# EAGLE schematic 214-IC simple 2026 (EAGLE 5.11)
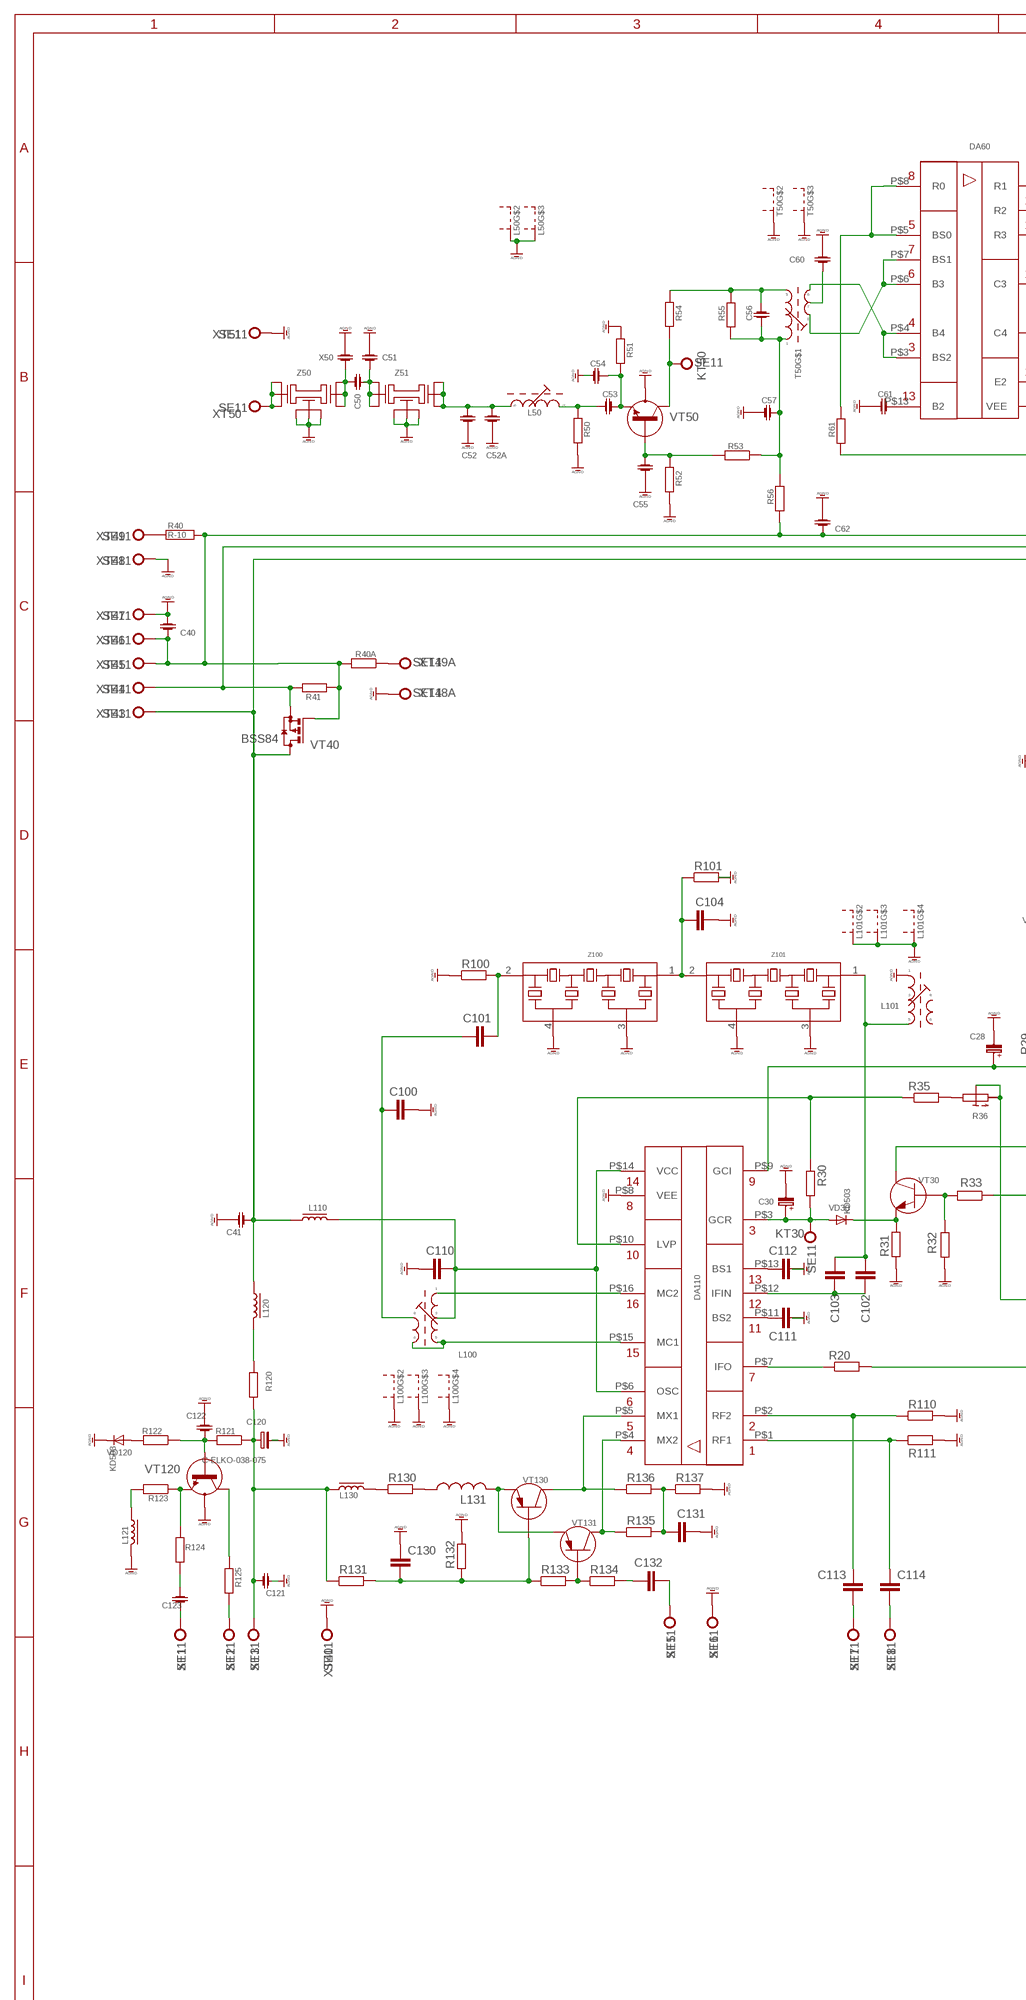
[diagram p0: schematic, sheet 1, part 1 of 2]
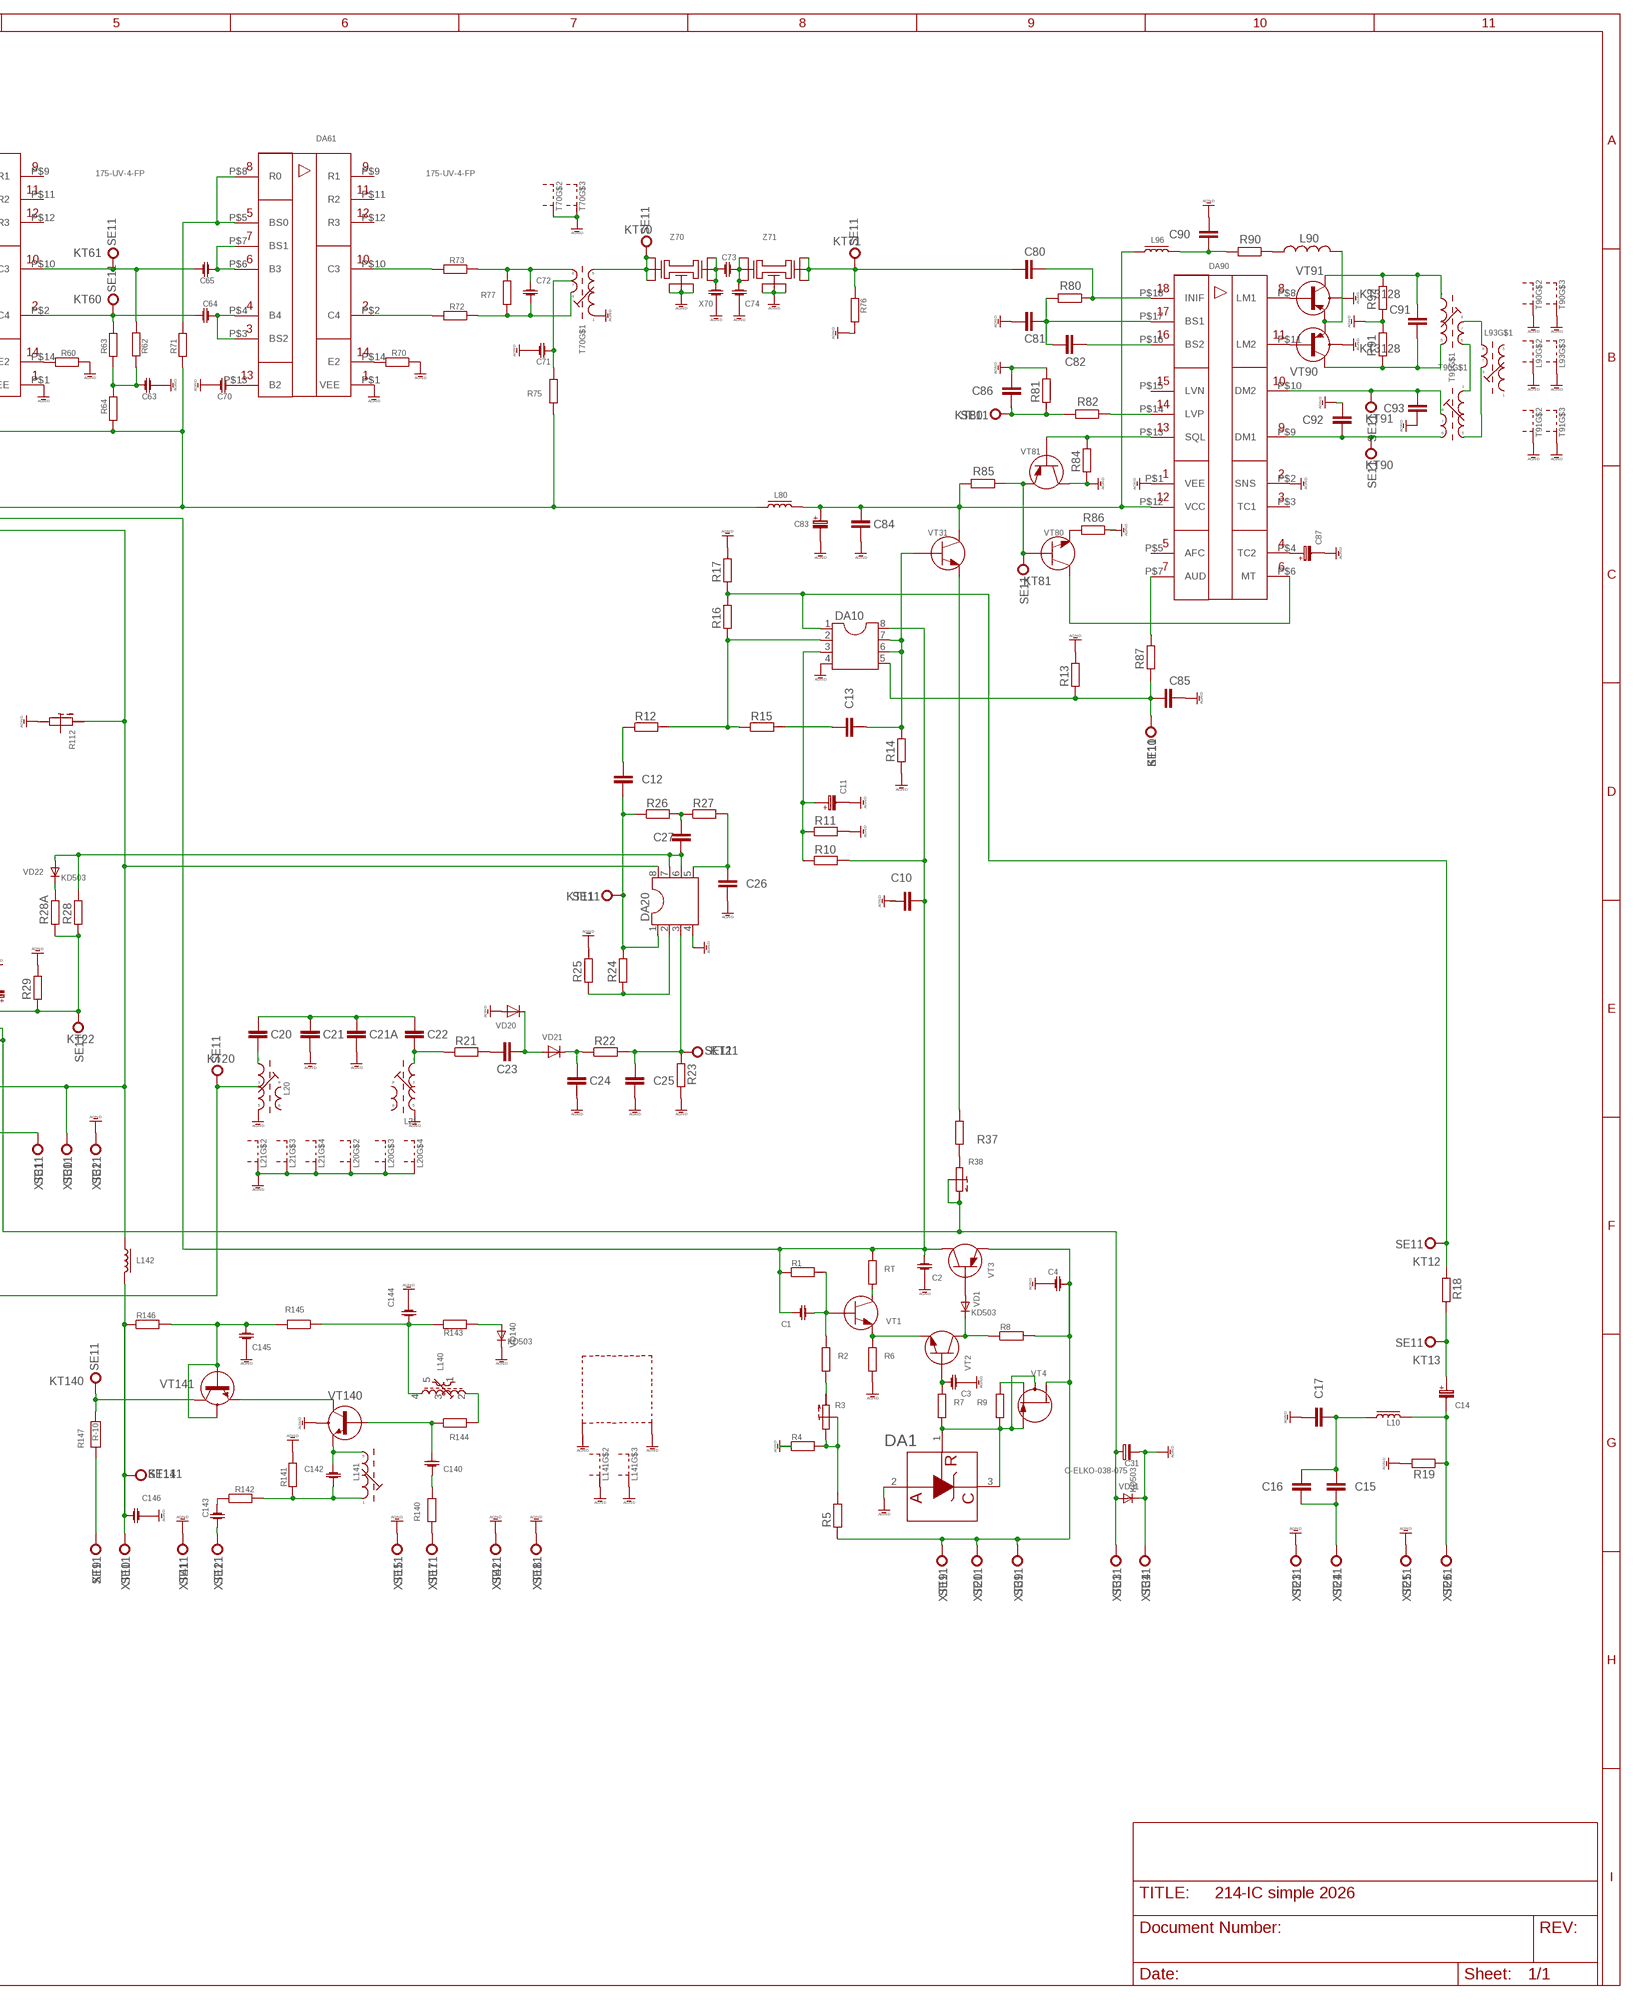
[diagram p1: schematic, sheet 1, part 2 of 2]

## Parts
C1  C-1206-0805  [RC-SMD-UNIV]
C2  C-1206-0805  [RC-SMD-UNIV]
C3  C-1206-0805  [RC-SMD-UNIV]
C4  C-1206-0805  [RC-SMD-UNIV]
C10  C-EUC1206  [C1206]
C11  CPOL-EUE2.5-5  [E2,5-5]
C12  C-EUC1206  [C1206]
C13  C-EUC1206  [C1206]
C14  CPOL-EUE2.5-5  [E2,5-5]
C15  C-EUC1206  [C1206]
C16  C-EUC1206  [C1206]
C17  C-EUC1206  [C1206]
C20  C-EUC1206  [C1206]
C21  C-EUC1206  [C1206]
C21A  C-EUC1206  [C1206]
C22  C-EUC1206  [C1206]
C23  C-EUC1206  [C1206]
C24  C-EUC1206  [C1206]
C25  C-EUC1206  [C1206]
C26  C-EUC1206  [C1206]
C27  C-EUC1206  [C1206]
C28  CPOL-EUE2.5-5  [E2,5-5]
C30  CPOL-EUE2.5-5  [E2,5-5]
C31  C-ELKO-038-075  [C-ELKO-038-075]
C40  C-1206-0805  [RC-SMD-UNIV]
C41  C-1206-0805  [RC-SMD-UNIV]
C50  C-1206-0805  [RC-SMD-UNIV]
C51  C-1206-0805  [RC-SMD-UNIV]
C52  C-1206-0805  [RC-SMD-UNIV]
C52A  C-1206-0805  [RC-SMD-UNIV]
C53  C-1206-0805  [RC-SMD-UNIV]
C54  C-1206-0805  [RC-SMD-UNIV]
C55  C-1206-0805  [RC-SMD-UNIV]
C56  C-1206-0805  [RC-SMD-UNIV]
C57  C-1206-0805  [RC-SMD-UNIV]
C60  C-1206-0805  [RC-SMD-UNIV]
C61  C-1206-0805  [RC-SMD-UNIV]
C62  C-1206-0805  [RC-SMD-UNIV]
C63  C-1206-0805  [RC-SMD-UNIV]
C64  C-1206-0805  [RC-SMD-UNIV]
C65  C-1206-0805  [RC-SMD-UNIV]
C70  C-1206-0805  [RC-SMD-UNIV]
C71  C-1206-0805  [RC-SMD-UNIV]
C72  C-1206-0805  [RC-SMD-UNIV]
C73  C-1206-0805  [RC-SMD-UNIV]
C74  C-1206-0805  [RC-SMD-UNIV]
C80  C-EUC1206  [C1206]
C81  C-EUC1206  [C1206]
C82  C-EUC1206  [C1206]
C83  CPOL-EUE2.5-5  [E2,5-5]
C84  C-EUC1206  [C1206]
C85  C-EUC1206  [C1206]
C86  C-EUC1206  [C1206]
C87  CPOL-EUE2.5-5  [E2,5-5]
C90  C-EUC1206  [C1206]
C91  C-EUC1206  [C1206]
C92  C-EUC1206  [C1206]
C93  C-EUC1206  [C1206]
C100  C-EUC1206  [C1206]
C101  C-EUC1206  [C1206]
C102  C-EUC1206  [C1206]
C103  C-EUC1206  [C1206]
C104  C-EUC1206  [C1206]
C110  C-EUC1206  [C1206]
C111  C-EUC1206  [C1206]
C112  C-EUC1206  [C1206]
C113  C-EUC1206  [C1206]
C114  C-EUC1206  [C1206]
C120  C-ELKO-038-075  [C-ELKO-038-075]
C121  C-1206-0805  [RC-SMD-UNIV]
C122  C-1206-0805  [RC-SMD-UNIV]
C123  C-1206-0805  [RC-SMD-UNIV]
C130  C-EUC1206  [C1206]
C131  C-EUC1206  [C1206]
C132  C-EUC1206  [C1206]
C140  C-1206-0805  [RC-SMD-UNIV]
C142  C-1206-0805  [RC-SMD-UNIV]
C143  C-1206-0805  [RC-SMD-UNIV]
C144  C-1206-0805  [RC-SMD-UNIV]
C145  C-1206-0805  [RC-SMD-UNIV]
C146  C-1206-0805  [RC-SMD-UNIV]
DA1  TL431  [TO92]
DA10  DIL8  [DIL08]
DA20  DIL8  [DIL08]
DA60  175-UV-4-FP  [401.14-5M-FP]
DA61  175-UV-4-FP  [401.14-5M-FP]
DA90  174XA6  [174XA-CERDIP-18]
DA110  174XA2  [174XA2-CERDIP-16]
KT10  SE11  [SE11]
KT11  SE11  [SE11]
KT12  SE11  [SE11]
KT13  SE11  [SE11]
KT20  SE11  [SE11]
KT21  SE11  [SE11]
KT22  SE11  [SE11]
KT30  SE11  [SE11]
KT50  SE11  [SE11]
KT60  SE11  [SE11]
KT61  SE11  [SE11]
KT70  SE11  [SE11]
KT71  SE11  [SE11]
KT80  SE11  [SE11]
KT81  SE11  [SE11]
KT90  SE11  [SE11]
KT91  SE11  [SE11]
KT140  SE11  [SE11]
KT141  SE11  [SE11]
L10  L-USL0603  [TOKO-RB10]
L20  214-N6-AMDET  [L-12-10]
L21  214-N6-AMDET  [L-12-10]
L50  209-N-L50  [L-7-MM]
L80  L-RUSS  [0309/20-RUSS]
L90  L-US  [L1206]
L93  T-7X7-SYMM  [L-7-MM]
L96  L-RUSS  [0309/20-RUSS]
L100  214-N6-AMDET  [L-12-10]
L101  214-N6-AMDET  [L-12-10]
L110  L-RUSS  [0309/20-RUSS]
L120  L-RUSS  [0309/20-RUSS]
L121  L-RUSS  [0309/20-RUSS]
L130  L-RUSS  [0309/20-RUSS]
L131  L-US  [L1206]
L140  71-5-24153  [71-5]
L141  209-N-L50  [L-7-MM]
L142  L-RUSS  [0309/20-RUSS]
R1  R-EU_R1206  [R1206]
R2  R-EU_R1206  [R1206]
R3  R-TRIMM  [CA6-V]
R4  R-EU_R1206  [R1206]
R5  R-EU_0207/12  [0207/12]
R6  R-EU_R1206  [R1206]
R7  R-EU_R1206  [R1206]
R8  R-EU_R1206  [R1206]
R9  R-EU_R1206  [R1206]
R10  R-EU_R1206  [R1206]
R11  R-EU_R1206  [R1206]
R12  R-EU_R1206  [R1206]
R13  R-EU_R1206  [R1206]
R14  R-EU_R1206  [R1206]
R15  R-EU_R1206  [R1206]
R16  R-EU_R1206  [R1206]
R17  R-EU_R1206  [R1206]
R18  R-EU_R1206  [R1206]
R19  R-EU_R1206  [R1206]
R20  R-EU_0207/12  [0207/12]
R21  R-EU_R1206  [R1206]
R22  R-EU_R1206  [R1206]
R23  R-EU_R1206  [R1206]
R24  R-EU_R1206  [R1206]
R25  R-EU_R1206  [R1206]
R26  R-EU_R1206  [R1206]
R27  R-EU_R1206  [R1206]
R28  R-EU_R1206  [R1206]
R28A  R-EU_R1206  [R1206]
R29  R-EU_R1206  [R1206]
R30  R-EU_0207/12  [0207/12]
R31  R-EU_R1206  [R1206]
R32  R-EU_R1206  [R1206]
R33  R-EU_R1206  [R1206]
R35  R-EU_0207/12  [0207/12]
R36  R-TRIMM  [CA6-V]
R37  R-EU_0207/12  [0207/12]
R38  R-TRIMM  [CA6-V]
R40  R-10  [R-10]
R40A  R-EU_R1206  [R1206]
R41  R-EU_R1206  [R1206]
R50  R-EU_R1206  [R1206]
R51  R-EU_R1206  [R1206]
R52  R-EU_R1206  [R1206]
R53  R-EU_R1206  [R1206]
R54  R-EU_R1206  [R1206]
R55  R-EU_R1206  [R1206]
R56  R-EU_R1206  [R1206]
R60  R-EU_R1206  [R1206]
R61  R-EU_R1206  [R1206]
R62  R-EU_R1206  [R1206]
R63  R-EU_R1206  [R1206]
R64  R-EU_R1206  [R1206]
R70  R-EU_R1206  [R1206]
R71  R-EU_R1206  [R1206]
R72  R-EU_R1206  [R1206]
R73  R-EU_R1206  [R1206]
R75  R-EU_R1206  [R1206]
R76  R-EU_R1206  [R1206]
R77  R-EU_R1206  [R1206]
R80  R-EU_R1206  [R1206]
R81  R-EU_R1206  [R1206]
R82  R-EU_R1206  [R1206]
R84  R-EU_R1206  [R1206]
R85  R-EU_R1206  [R1206]
R86  R-EU_R1206  [R1206]
R87  R-EU_0207/12  [0207/12]
R90  R-EU_R1206  [R1206]
R91  R-EU_R1206  [R1206]
R92  R-EU_R1206  [R1206]
R100  R-EU_R1206  [R1206]
R101  R-EU_R1206  [R1206]
R110  R-EU_R1206  [R1206]
R111  R-EU_R1206  [R1206]
R112  R-TRIMM  [CA6-V]
R120  R-EU_R1206  [R1206]
R121  R-EU_R1206  [R1206]
R122  R-EU_R1206  [R1206]
R123  R-EU_R1206  [R1206]
R124  R-EU_R1206  [R1206]
R125  R-EU_R1206  [R1206]
R130  R-EU_R1206  [R1206]
R131  R-EU_R1206  [R1206]
R132  R-EU_R1206  [R1206]
R133  R-EU_R1206  [R1206]
R134  R-EU_R1206  [R1206]
R135  R-EU_R1206  [R1206]
R136  R-EU_R1206  [R1206]
R137  R-EU_R1206  [R1206]
R140  R-EU_R1206  [R1206]
R141  R-EU_R1206  [R1206]
R142  R-EU_R1206  [R1206]
R143  R-EU_R1206  [R1206]
R144  R-EU_R1206  [R1206]
R145  R-EU_R1206  [R1206]
R146  R-EU_R1206  [R1206]
R147  R-10  [R-10]
RT  R-EU_R1206  [R1206]
T50  T-7X7-SYMM  [L-7-MM]
T70  T-7X7-SYMM  [L-7-MM]
T90  T-7X7-SYMM  [L-7-MM]
T91  T-7X7-SYMM  [L-7-MM]
VD1  KD503  AA112  [DO07]
VD20  VD-15-GLAS  [VD-OLD-GLASS]
VD21  VD-15-GLAS  [VD-OLD-GLASS]
VD22  KD503  AA112  [DO07]
VD30  KD503  AA112  [DO07]
VD31  KD503  AA112  [DO07]
VD120  KD503  AA112  [DO07]
VD140  KD503  AA112  [DO07]
VT1  VT-KT368  [VT-TO-18-3]
VT2  VT-KT368  [VT-TO-18-3]
VT3  VT-KT326  [VT-TO-18-3]
VT4  VT-KP303  [VT-TO-18-4]
VT30  VT-KT368  [VT-TO-18-3]
VT31  VT-KT368  [VT-TO-18-3]
VT40  BSS84  [SOT23]
VT50  KT368  [TO72B]
VT80  VT-KT368  [VT-TO-18-3]
VT81  VT-KT326  [VT-TO-18-3]
VT90  KT3128  [TO72B]
VT91  KT3128  [TO72B]
VT120  KT368  [TO72B]
VT130  VT-KT326  [VT-TO-18-3]
VT131  VT-KT326  [VT-TO-18-3]
VT140  KT368  [TO72B]
VT141  KT368  [TO72B]
X50  C-1206-0805  [RC-SMD-UNIV]
X70  C-1206-0805  [RC-SMD-UNIV]
XT1  SE11  [SE11]
XT2  SE11  [SE11]
XT3  SE11  [SE11]
XT5  SE11  [SE11]
XT6  SE11  [SE11]
XT7  SE11  [SE11]
XT8  SE11  [SE11]
XT9  SE11  [SE11]
XT10  SE11  [SE11]
XT12  SE11  [SE11]
XT15  SE11  [SE11]
XT17  SE11  [SE11]
XT18  SE11  [SE11]
XT19  SE11  [SE11]
XT20  SE11  [SE11]
XT23  SE11  [SE11]
XT24  SE11  [SE11]
XT25  SE11  [SE11]
XT26  SE11  [SE11]
XT30  SE11  [SE11]
XT31  SE11  [SE11]
XT32  SE11  [SE11]
XT33  SE11  [SE11]
XT34  SE11  [SE11]
XT39  SE11  [SE11]
XT40  SE11  [SE11]
XT41  SE11  [SE11]
XT42  SE11  [SE11]
XT43  SE11  [SE11]
XT44  SE11  [SE11]
XT45  SE11  [SE11]
XT46  SE11  [SE11]
XT47  SE11  [SE11]
XT48  SE11  [SE11]
XT48A  SE11  [SE11]
XT49  SE11  [SE11]
XT49A  SE11  [SE11]
XT50  SE11  [SE11]
XT51  SE11  [SE11]
Z50  PKF-10700-N  [PKF-10700-U-N]
Z51  PKF-10700-N  [PKF-10700-U-N]
Z70  PKF-10700-N  [PKF-10700-U-N]
Z71  PKF-10700-N  [PKF-10700-U-N]
Z100  FP1P1-60  [FP1P1-60]
Z101  FP1P1-60  [FP1P1-60]

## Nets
AGND: C2.P$2 C3.P$2 C4.P$1 C10.2 C11.- C17.2 C21.1 C21A.1 C24.1 C25.1 C26.1 C28.- C30.- C31.P$1 C40.P$1 C41.P$2 C51.P$1 C52.P$2 C52A.P$2 C54.P$1 C55.P$2 C57.P$1 C60.P$1 C61.P$2 C62.P$1 C63.P$2 C70.P$1 C71.P$1 C74.P$2 C81.1 C83.- C84.2 C85.2 C86.1 C87.- C90.1 C92.1 C93.2 C100.1 C104.2 C110.2 C111.2 C112.2 C120.P$1 C121.P$2 C122.P$1 C130.1 C131.2 C144.P$2 C145.P$2 C146.P$1 DA1.2 DA10.4 DA20.4 DA60.P$1(VEE) DA61.P$1(VEE) DA90.P$1(VEE) DA90.P$2(SNS) DA110.P$8(VEE) L20.5 L20.11(S) L20.14(S) L20.15(S) L21.5 L21.11(S) L21.14(S) L21.15(S) L50.P$6(S) L50.P$7(S) L93.P$6(S) L93.P$7(S) L100.11(S) L100.14(S) L100.15(S) L101.1 L101.11(S) L101.14(S) L101.15(S) L121.2 L140.S1 L140.S2 L141.P$6(S) L141.P$7(S) R4.1 R6.2 R11.2 R13.2 R14.1 R17.2 R19.2 R23.2 R25.2 R29.2 R31.1 R32.2 R50.1 R51.2 R52.1 R60.1 R70.1 R76.2 R81.2 R84.1 R86.1 R91.2 R92.1 R100.1 R101.2 R110.2 R111.2 R112.E R132.2 R137.2 R141.2 T50.P$6(S) T50.P$7(S) T70.5 T70.P$6(S) T70.P$7(S) T90.P$6(S) T90.P$7(S) T91.P$6(S) T91.P$7(S) VD20.P$1 VD31.C VD120.C VD140.C VT50.GEH(H) VT81.3(C) VT90.GEH(H) VT91.GEH(H) VT120.GEH(H) VT140.GEH(H) X50.P$1 X70.P$2 XT6.MP XT15.MP XT18.MP XT23.MP XT25.MP XT32.MP XT34.MP XT40.MP XT41.MP XT42.MP XT47.MP XT48.MP XT48A.MP XT51.MP Z50.P$4 Z50.P$5 Z50.P$6 Z51.P$4 Z51.P$5 Z51.P$6 Z70.P$4 Z70.P$5 Z70.P$6 Z71.P$4 Z71.P$5 Z71.P$6 Z100.3 Z100.4 Z101.3 Z101.4
N$1: C50.P$1 X50.P$2 Z50.P$7 Z50.P$8 Z50.P$9
N$2: C114.1 DA110.P$1(RF1) R111.1
N$3: DA90.P$8(LM1) VT91.B
N$4: C28.+ DA110.P$9(GCI) KT22.MP R28.1 R28A.1 R29.1
N$5: DA90.P$11(LM2) VT90.B
N$6: C113.1 DA110.P$2(RF2) R110.1
N$7: R3.E R3.S R4.2 R5.2
N$8: C113.2 XT7.MP
N$9: C114.2 XT8.MP
N$10: L131.2 VT130.1(E) VT131.1(E)
N$11: L131.1 R130.2
N$12: L130.2 R130.1
N$13: DA110.P$5(MX1) R136.1 VT130.3(C)
N$14: DA110.P$4(MX2) R135.1 VT131.3(C)
N$15: DA110.P$10(LVP) R30.1 R35.1
N$16: C131.1 R135.2 R136.2 R137.1
N$17: R133.2 R134.1 VT131.2(B)
N$18: C130.2 R131.2 R132.1 R133.1 VT130.2(B)
N$19: C132.1 R134.2
N$20: C132.2 XT5.MP
N$21: C146.P$2 KT141.MP L142.2 R146.1 XT10.MP
N$22: L121.1 R123.2
N$23: C87.+ DA90.P$4(TC2)
N$24: C110.1 DA110.P$6(OSC) DA110.P$14(VCC) L100.3 L110.2
N$25: VD1.A VT3.2(B)
N$26: C112.1 DA110.P$13(BS1)
N$27: C104.1 R101.1 Z100.1 Z101.2
N$28: R8.1 VD1.C VT2.3(C)
N$29: C102.1 C103.1 DA110.P$12(IFIN)
N$30: R28A.2 VD22.C
N$31: C102.2 C103.2 L101.5 Z101.1
N$32: DA110.P$16(MC2) L100.1
N$33: DA110.P$15(MC1) L100.5 L100.6
N$34: C101.2 R100.2 Z100.2
N$35: R122.2 VD120.A
N$36: R35.2 R36.E
N$37: DA60.P$14(E2) R60.2
N$38: C14.- L10.P$2 R19.1 XT26.MP
N$39: DA90.P$7(AUD) R87.2
N$40: C14.+ KT13.MP R18.2
N$41: DA110.P$7(IFO) R20.1
N$42: C1.P$1 C2.P$1 C10.1 DA10.8 R1.1 R10.2 R41.2 RT.1 VT3.3(C) VT40.2(S) XT44.MP
N$43: KT20.MP L20.3 R20.2
N$44: R31.2 VD30.C VT30.1(E)
N$46: C142.P$2 L141.3 VT140.E
N$47: R32.1 R33.2 VT30.2(B)
N$48: DA61.P$14(E2) R70.2
N$49: C30.+ DA110.P$3(GCR) KT30.MP R30.2 VD30.A
N$50: C86.2 KT80.MP R81.1 R82.2
N$51: L90.2 VT90.E VT91.E
N$52: R2.2 R3.A
N$53: DA1.1 DA1.3 R7.2 R9.2 VT4.3(G) VT4.4(SH)
N$54: R6.1 VT1.1(E) VT2.1(E)
N$55: C4.P$2 R5.1 R8.2 VT3.1(E) VT4.2(D) XT19.MP XT20.MP XT39.MP
N$56: C3.P$1 R7.1 VT2.2(B)
N$57: R140.2 XT17.MP
N$58: C1.P$2 R1.2 R2.1 VT1.2(B)
N$59: C140.P$1 R144.1 VT140.B
N$60: C142.P$1 L141.1 R141.1 R142.2
N$61: C80.1 KT71.MP R76.1 Z71.P$7 Z71.P$8 Z71.P$9
N$62: C73.P$2 C74.P$1 Z71.P$1 Z71.P$2 Z71.P$3
N$63: C63.P$1 R62.1 R63.2 R64.1
N$64: C73.P$1 X70.P$1 Z70.P$7 Z70.P$8 Z70.P$9
N$65: C65.P$1 DA60.P$10(C3) KT61.MP R62.2
N$66: DA60.P$5(BS0) DA60.P$8(R0) R61.1
N$67: C56.P$2 R54.2 R55.1 T50.4
N$68: VT140.C VT141.E
N$69: L140.2(A1) R144.2
N$70: C52.P$1 C52A.P$1 L50.3 Z51.P$7 Z51.P$8 Z51.P$9
N$71: DA60.P$3(BS2) DA60.P$4(B4) T50.3
N$72: DA60.P$6(B3) DA60.P$7(BS1) T50.1
N$73: C140.P$2 R140.1
N$74: C83.+ C84.1 DA90.P$12(VCC) L80.2 L96.1 R85.2 VT31.3(C)
N$75: C20.1 L20.1
N$76: C22.1 L21.1 R21.1
N$77: C61.P$1 DA60.P$13(B2)
N$78: C53.P$2 L50.1 R50.2
N$79: C53.P$1 C54.P$2 R51.1 VT50.E
N$80: DA61.P$5(BS0) DA61.P$8(R0) R71.1
N$81: C20.2 C21.2 C21A.2 C22.2
N$82: C23.1 R21.2
N$83: C123.P$1 R124.1
N$84: C23.2 VD20.P$2 VD21.P$1
N$85: C24.2 R22.1 VD21.P$2
N$86: C25.2 DA20.3 KT21.MP R22.2 R23.1
N$88: KT70.MP T70.4 Z70.P$1 Z70.P$2 Z70.P$3
N$89: C91.1 R92.2 T90.5 VT91.C
N$90: C91.2 R91.1 T90.4 VT90.C
N$91: C93.1 DA90.P$10(DM2) KT91.MP T91.1
N$92: C92.2 DA90.P$9(DM1) KT90.MP T91.3
N$93: L93.3 T90.1
N$94: L93.1 T91.4
N$95: T90.3 T91.5
N$96: L90.1 R90.1
N$97: C90.2 L96.2 R90.2
N$98: C80.2 DA90.P$18(INIF) R80.1
N$99: C81.2 C82.1 DA90.P$17(BS1) R80.2
N$100: C82.2 DA90.P$16(BS2)
N$101: DA90.P$14(LVP) R82.1
N$102: DA90.P$13(SQL) R84.2 VT81.2(B)
N$103: KT81.MP R85.1 VT80.2(B) VT81.1(E)
N$104: R86.2 VT80.1(E)
N$105: C50.P$2 C51.P$2 Z51.P$1 Z51.P$2 Z51.P$3
N$106: C120.P$2 C121.P$1 L130.1 R120.1 R121.1 R131.1 XT3.MP
N$107: DA90.P$6(MT) VT80.3(C)
N$108: R37.2 VT31.1(E)
N$109: R37.1 R38.E
N$110: C31.P$2 R36.A R36.S R38.A R38.S VD31.A XT33.MP
N$111: C85.1 DA10.5 KT10.MP R13.1 R87.1
N$112: R33.1 XT31.MP
N$113: C12.1 DA20.1 KT11.MP R24.2 R26.1
N$114: DA20.2 R24.1 R25.1
N$115: C27.1 DA20.6 DA20.7 R28.2 VD22.A
N$116: C143.P$1 XT12.MP
N$117: C143.P$2 R142.1
N$118: C144.P$1 L140.4(E1) R143.1 R145.1
N$119: C41.P$1 DA20.8 L110.1 L120.1 L142.1 R112.A VT30.3(C) VT40.3(D) XT30.MP XT43.MP
N$120: C27.2 R26.2 R27.1
N$121: C26.2 DA20.5 R27.2
N$122: C145.P$1 R145.2 R146.2 VT141.B VT141.GEH(H)
N$123: C12.2 R12.1
N$124: C13.2 R15.2
N$125: KT140.MP R147.P$1 VT141.C
N$126: R147.P$2 XT9.MP
N$127: C13.1 DA10.6 DA10.7 R14.2 VT31.2(B)
N$128: XT50.MP Z50.P$1 Z50.P$2 Z50.P$3
N$129: DA10.2 R12.2 R15.1 R16.1
N$130: C15.1 C16.2 XT24.MP
N$131: C65.P$2 DA61.P$6(B3) DA61.P$7(BS1)
N$132: C55.P$1 R52.2 R53.2 VT50.B
N$133: DA10.1 KT12.MP R16.2 R17.1 R18.1
N$134: C11.+ DA10.3 R10.1 R11.1
N$135: KT50.MP R54.1 VT50.C
N$136: R40.P$1 XT49.MP
N$137: C15.2 C16.1 C17.1 L10.P$1
N$138: C123.P$2 XT1.MP
N$139: C40.P$2 C62.P$2 L80.1 R40.P$2 R40A.2 R41.1 R56.2 R61.2 R64.2 R71.2 R75.2 VT40.1(G) XT45.MP XT46.MP
N$140: R40A.1 XT49A.MP
N$141: C100.2 C101.1 L100.8
N$145: R123.1 R124.2 VT120.E
N$146: RT.2 VT1.3(C)
N$148: C122.P$2 R121.2 R122.1 VT120.B
N$149: C111.1 DA110.P$11(BS2)
N$150: R125.1 XT2.MP
N$151: R125.2 VT120.C
N$165: R9.1 VT4.1(S)
N$172: R143.2 VD140.A
N$177: C64.P$1 DA61.P$3(BS2) DA61.P$4(B4)
N$190: L120.2 R120.2
N$221: C70.P$2 DA61.P$13(B2)
N$222: DA61.P$2(C4) R72.2
N$223: DA61.P$10(C3) R73.2
N$224: C72.P$1 R73.1 R77.1 T70.3
N$225: C72.P$2 R72.1 R77.2 T70.1
N$226: C56.P$1 C57.P$2 R53.1 R55.2 R56.1 T50.5
N$227: C71.P$2 R75.1 T70.2
N$228: C64.P$2 DA60.P$2(C4) KT60.MP R63.1
N$229: C60.P$2 T50.2
Unconnected: DA60.P$9(R1) DA60.P$11(R2) DA60.P$12(R3) DA61.P$9(R1) DA61.P$11(R2) DA61.P$12(R3) DA90.P$3(TC1) DA90.P$5(AFC) DA90.P$15(LVN) L20.6 L20.8 L21.3 L21.6 L21.8 L93.2 L93.4 L93.5 L101.3 L101.6 L101.8 L140.1(A2) L140.3(Z) L140.5(E2) R112.S T90.2 T91.2

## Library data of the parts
C1-C4 C40 C41 C50-C52 C52A C53-C57 C60-C65 C70-C74 C121-C123 C140 C142-C146 X50 X70 = OKEAH:C-1206-0805
C10 C12 C13 C15-C17 C20 C21 C21A C22-C27 C80-C82 C84-C86 C90-C93 C100-C104 C110-C114 C130-C132 = rlc:C-EU: CAPACITOR, European symbol
C11 C14 C28 C30 C83 C87 = rcl:CPOL-EU: POLARIZED CAPACITOR, European symbol
C31 C120 = OKEAH:C-ELKO-038-075
DA1 = linear:TL431
DA10 DA20 = IC packages:DIL8: Dual In Line / Socket
DA60 DA61 = RX systems:175-UV-4-FP
DA90 = RX systems:174XA6
DA110 = RX systems:174XA2
KT10-KT13 KT20-KT22 KT30 KT50 KT60 KT61 KT70 KT71 KT80 KT81 KT90 KT91 KT140 KT141 XT1-XT3 XT5-XT10 XT12 XT15 XT17-XT20 XT23-XT26 XT30-XT34 XT39-XT48 XT48A XT49 XT49A XT50 XT51 = solpad:SE11: SOLDER PAD
L10 = rcl:L-US: INDUCTOR, American symbol
L20 L21 L100 L101 = OKEAH:214-N6-AMDET
L50 L141 = OKEAH:209-N-L50
L80 L96 L110 L120 L121 L130 L142 = rcl:L-RUSS: DM and DMP chokes RUSSIA
L90 L131 = rlc:L-US: INDUCTOR, American symbol
L93 T50 T70 T90 T91 = OKEAH:T-7X7-SYMM
L140 = inductor-neosid:71-5-: TRANSFORMER adjustable filter transformer with tap; OC_FARNELL: unknown; OC_NEWARK: unknown
R1 R2 R4-R28 R28A R29-R33 R35 R37 R40A R41 R50-R56 R60-R64 R70-R73 R75-R77 R80-R82 R84-R87 R90-R92 R100 R101 R110 R111 R120-R125 R130-R137 R140-R146 RT = rlc:R-EU_: RESISTOR, European symbol
R3 R36 R38 R112 = rcl:R-TRIMM: Trimm resistor
R40 R147 = OKEAH:R-10
VD1 VD22 VD30 VD31 VD120 VD140 = diode:AA112: DIODE
VD20 VD21 = OKEAH:VD-15-GLAS
VT1 VT2 VT30 VT31 VT80 = OKEAH:VT-KT368
VT3 VT81 VT130 VT131 = OKEAH:VT-KT326
VT4 = OKEAH:VT-KP303
VT40 = VT small signal:BSS84: P-CHANNEL MOS FET
VT50 VT120 VT140 VT141 = VT small signal:KT368
VT90 VT91 = VT small signal:KT3128
Z50 Z51 Z70 Z71 = OKEAH:PKF-10700-N
Z100 Z101 = filter 455 450:FP1P1-60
